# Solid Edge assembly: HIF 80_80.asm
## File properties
Title: Zylinder
Author: ahadarics
Template: iso assembly.asm
Last saved by: ahadarics
Revision: 22
Application: Solid Edge
Username: ahadarics
Dokumentum tartalom típus: 1
Document Number: HIF 80/80
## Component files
Kit_2.par
Kit_1.par
Profilrohr 80_80.par
Kolbenstange 80_80.par
Mutter.par
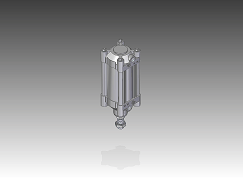
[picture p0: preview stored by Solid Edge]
